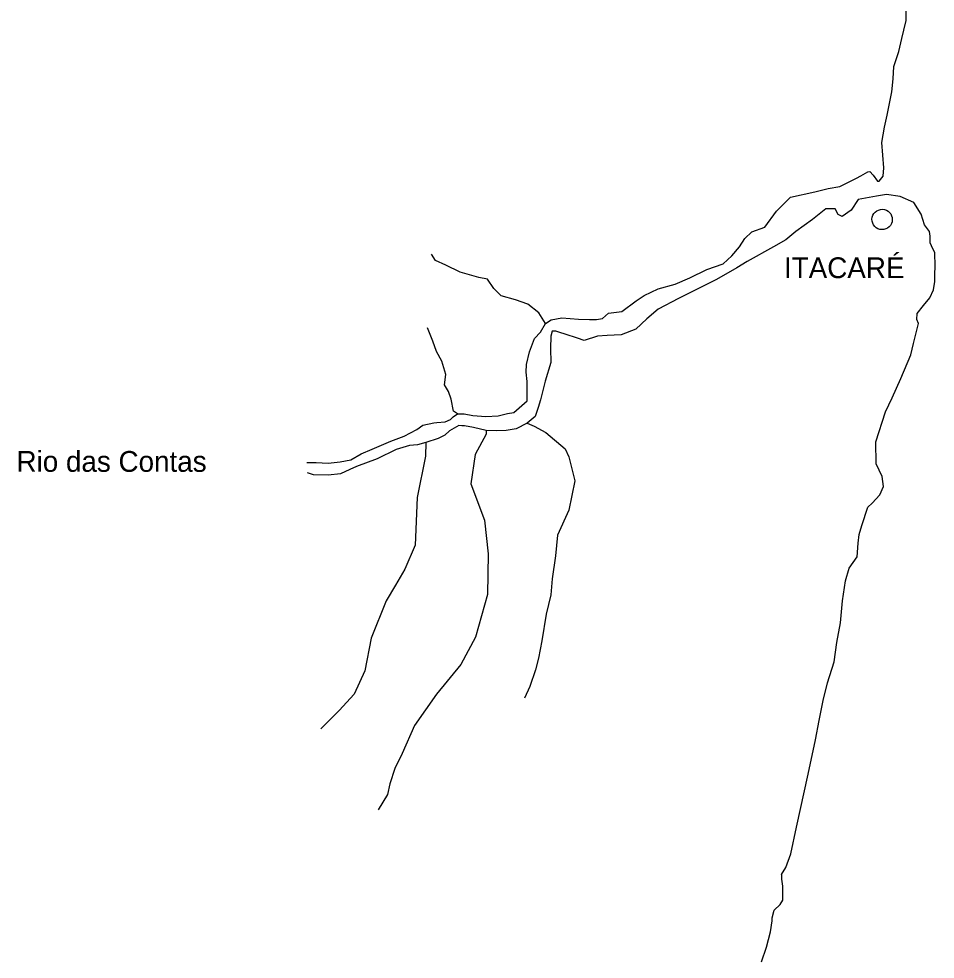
# Model space of a CAD drawing. Extents: x 662444 to 1640468, y 7452018 to 9606170.
# Drawn here: x 1121017 to 1150327, y 8389481 to 8419546 of the extents above; entities that cross this region are included whole.
import ezdxf

# ---------------------------------------------------------------- set-up
doc = ezdxf.new("R2010")
doc.units = 0
for name, color, linetype in [('Level 1', 7, 'Continuous'), ('Level 2', 7, 'Continuous'), ('Level 3', 7, 'Continuous')]:
    doc.layers.add(name, color=color, linetype=linetype)

msp = doc.modelspace()

# ---------------------------------------------------------------- linework, layer by layer
at = {"layer": 'Level 1'}
for points in [[(1130227, 8405363), (1130530, 8405356), (1130909, 8405335), (1131300, 8405381), (1131638, 8405450), (1131968, 8405642), (1132319, 8405788), (1132921, 8406040), (1133338, 8406207), (1133744, 8406419), (1133943, 8406559), (1134291, 8406628), (1134389, 8406636), (1134650, 8406663), (1134825, 8406736), (1134914, 8406823), (1135047, 8406920), (1135112, 8406918), (1135264, 8406914), (1135544, 8406863), (1135955, 8406830), (1136346, 8406853), (1136651, 8406923), (1136848, 8406963), (1137280, 8407330), (1137274, 8407953), (1137249, 8408253), (1137255, 8408498), (1137352, 8408896), (1137515, 8409325), (1137705, 8409532), (1137864, 8409805), (1138040, 8409923), (1138389, 8409981), (1138919, 8409945), (1139266, 8409936), (1139493, 8409931), (1139689, 8409970), (1139878, 8410132), (1140302, 8410188), (1140766, 8410532), (1141020, 8410703), (1141470, 8410914), (1142006, 8411067), (1142477, 8411266), (1143026, 8411530), (1143541, 8411717), (1143818, 8411966), (1144064, 8412259), (1144234, 8412522), (1144467, 8412738), (1144883, 8412883), (1145254, 8413396), (1145699, 8413841), (1146474, 8414010), (1146900, 8414121), (1147281, 8414189), (1147808, 8414454), (1147951, 8414528), (1148172, 8414656), (1148237, 8414665), (1148343, 8414551), (1148479, 8414358), (1148533, 8414357), (1148667, 8414520), (1148685, 8414787), (1148619, 8415589), (1148708, 8416087), (1148793, 8416463), (1148943, 8417216), (1148986, 8417626), (1149007, 8418026), (1149161, 8418500), (1149258, 8418920), (1149319, 8419186), (1149403, 8419495), (1149394, 8419962)], [(1145707, 8392845), (1145892, 8393707), (1146261, 8395399), (1146496, 8396494), (1146620, 8397113), (1146745, 8397755), (1146879, 8398319), (1147092, 8398992), (1147184, 8399601), (1147298, 8400232), (1147360, 8400942), (1147463, 8401573), (1147571, 8401982), (1147830, 8402342), (1147863, 8402786), (1147892, 8403063), (1147986, 8403350), (1148175, 8403935), (1148309, 8404065), (1148554, 8404325), (1148669, 8404589), (1148634, 8404912), (1148439, 8405318), (1148425, 8406019), (1148742, 8406978), (1148949, 8407429), (1149225, 8408044), (1149549, 8408803), (1149634, 8409168), (1149792, 8409809), (1149741, 8409933), (1149746, 8410122), (1149948, 8410383), (1150160, 8410622), (1150276, 8410886), (1150315, 8411152), (1150321, 8411386), (1150327, 8411630), (1150317, 8412075), (1150255, 8412188), (1150163, 8412380), (1150168, 8412602), (1150140, 8412747), (1149983, 8412963), (1149883, 8413299), (1149643, 8413672), (1149203, 8413861), (1148771, 8413928), (1148455, 8413881), (1147867, 8413774), (1147641, 8413424), (1147354, 8413231), (1147225, 8413290), (1147132, 8413470), (1146828, 8413467), (1146408, 8413133), (1145866, 8412747), (1145545, 8412477), (1145159, 8412253), (1144312, 8411786), (1143982, 8411583), (1143332, 8411211), (1142651, 8410872), (1142113, 8410608), (1141464, 8410258), (1141099, 8409956), (1140754, 8409620), (1140283, 8409443), (1139838, 8409421), (1139523, 8409396), (1139097, 8409262), (1138892, 8409334), (1138764, 8409382), (1138624, 8409419), (1138194, 8409564), (1138074, 8409555), (1138038, 8409401), (1138027, 8409001), (1138038, 8408556), (1137849, 8407960), (1137704, 8407363), (1137632, 8407121), (1137538, 8406834), (1137272, 8406618), (1136921, 8406438), (1136605, 8406380), (1136291, 8406377), (1135966, 8406385), (1135556, 8406484), (1135276, 8406536), (1135189, 8406538), (1135091, 8406541), (1134794, 8406370), (1134639, 8406230), (1134430, 8406124), (1134037, 8406000), (1133764, 8405930), (1133514, 8405903), (1133088, 8405780), (1132484, 8405473), (1131817, 8405234)], [(1137864, 8409805), (1137655, 8410144), (1137294, 8410420), (1136907, 8410564), (1136444, 8410687), (1136212, 8410926), (1136013, 8411220), (1135732, 8411272), (1135130, 8411443), (1134680, 8411666), (1134348, 8411819), (1134212, 8412022)], [(1135047, 8406920), (1134919, 8407001), (1134842, 8407381), (1134761, 8407628), (1134637, 8407842), (1134678, 8408174), (1134548, 8408600), (1134382, 8408905), (1134260, 8409241), (1134087, 8409668)], [(1137272, 8406618), (1137498, 8406524), (1137872, 8406325), (1138487, 8405798), (1138611, 8405539), (1138797, 8404778), (1138610, 8403837), (1138243, 8403035), (1138183, 8402381), (1138077, 8401638), (1138031, 8401128), (1137885, 8400509), (1137744, 8399657), (1137643, 8399103), (1137547, 8398728), (1137360, 8398199), (1137188, 8397825)], [(1135966, 8406385), (1135962, 8406263), (1135610, 8405616), (1135477, 8404674), (1135914, 8403517), (1136027, 8402436), (1136005, 8401136), (1135623, 8399778), (1135156, 8398900), (1134373, 8397953), (1133676, 8396948), (1133284, 8396057), (1133044, 8395574), (1132880, 8395089), (1132807, 8394746), (1132512, 8394254)], [(1134037, 8406000), (1134026, 8405567), (1133754, 8404240), (1133693, 8402718), (1133359, 8401948), (1133064, 8401444), (1132770, 8400940), (1132284, 8399741), (1132084, 8398701), (1131740, 8397954), (1131261, 8397432), (1130682, 8396847)], [(1131817, 8405234), (1131609, 8405139), (1131302, 8405003), (1130910, 8404957), (1130444, 8404969), (1130251, 8405029)], [(1144771, 8389399), (1144935, 8389862), (1145056, 8390359), (1145109, 8390703), (1145111, 8390803), (1145172, 8391046), (1145372, 8391230), (1145451, 8391372), (1145452, 8391817), (1145425, 8392040), (1145418, 8392163), (1145408, 8392185), (1145554, 8392415), (1145707, 8392845)]]:
    msp.add_lwpolyline(points, dxfattribs=at)
at = {"layer": 'Level 2'}
msp.add_ellipse((1148631, 8413131), major_axis=(325, -8), ratio=0.999997, dxfattribs=at)

# ---------------------------------------------------------------- texts
at = {"layer": 'Level 3'}
for s, height, p in [('ITACARÉ', 665.4, (1145490, 8411255)), ('Rio das Contas', 665.03, (1120944, 8405063))]:
    msp.add_text(s, height=height, dxfattribs=at).set_placement(p)

doc.saveas('drawing.dxf')
